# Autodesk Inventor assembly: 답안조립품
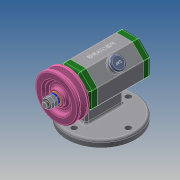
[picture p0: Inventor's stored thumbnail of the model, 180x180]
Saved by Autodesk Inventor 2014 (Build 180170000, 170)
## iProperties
Created: 2021-02
Part Number: 답안조립품
Document SubType Name: Assembly
Designer: kb542
Author: kb542
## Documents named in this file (14)
- C:\Users\kb542\Documents\Inventor\710204V1014\답안조립품.iam
- C:\Users\kb542\Documents\Inventor\710204V1014\본체.ipt
- C:\Users\kb542\Documents\Inventor\710204V1014\710204V1014\V벨트풀리.ipt
- C:\Users\kb542\Documents\Inventor\710204V1014\710204V1014\고무캡.ipt
- C:\Users\kb542\Documents\Inventor\710204V1014\710204V1014\너트 M8.ipt
- C:\Users\kb542\Documents\Inventor\710204V1014\710204V1014\뒤커버.ipt
- C:\Users\kb542\Documents\Inventor\710204V1014\710204V1014\베어링 15 x 32 x 9.ipt
- C:\Users\kb542\Documents\Inventor\710204V1014\710204V1014\볼트 M4 x 12.ipt
- C:\Users\kb542\Documents\Inventor\710204V1014\710204V1014\스프링와셔 8.ipt
- C:\Users\kb542\Documents\Inventor\710204V1014\710204V1014\앞커버.ipt
- C:\Users\kb542\Documents\Inventor\710204V1014\710204V1014\오일 실 15 25 7.ipt
- C:\Users\kb542\Documents\Inventor\710204V1014\710204V1014\와셔 8x17.ipt
- C:\Users\kb542\Documents\Inventor\710204V1014\710204V1014\축.ipt
- C:\Users\kb542\Documents\Inventor\710204V1014\710204V1014\키 3 x 3 x 12.ipt
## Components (2 placed, 2 different names)
1. V벨트풀리:1 — 각도:1
2. 고무캡:1 — 각도:4
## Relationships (2: Angle 2)
- 각도:1 [Angle]: V벨트풀리:1
- 각도:4 [Angle]: 고무캡:1
